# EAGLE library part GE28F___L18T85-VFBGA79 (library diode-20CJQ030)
Intel StrataFlash® Wireless Memory (L18) 28F640L18, 28F128L18, 28F256L18 Package: VFBGA-79 Description: The Intel StrataFlash® wireless memory (L18) device is the latest generation of Intel StrataFlash® memory devices featuring flexible, multiple-partition, dual operation. It provides high performance synchronous-burst read mode and asynchronous read mode using 1.8 V lowvoltage, multi-level cell (MLC) technology. High performance Read-While-Write/Erase -85 ns initial access -54 MHz with zero wait state, 14 ns clock-todata output synchronous-burst mode -25 ns asynchronous-page mode -4-, 8-, 16-, and continuous-word burst mode -Burst suspend -Programmable WAIT configuration -Buffered Enhanced Factory Programming (Buffered EFP): 5 µs/byte (Typ) -1.8 V low-power buffered and non-buffered programming at 7 µs/byte (Typ) Architecture -Asymmetrically-blocked architecture -Multiple 8-Mbit partitions: 64Mb and 128Mb devices -Multiple 16-Mbit partitions: 256Mb devices -Four 16-Kword parameter blocks: top or bottom configurations -64-Kword main blocks -Dual-operation: Read-While-Write (RWW) or Read-While-Erase (RWE) -Status register for partition and device status Power -1.7 V - 2.0 V VCC operation -I/O voltage: 1.35 V - 2.0 V, 1.7 V - 2.0 V -Standby current: 25 µA (Typ) -4-Word synchronous read current: 17 mA (Typ) at 54 MHz -Automatic Power Savings (APS) mode Please send any comments to: messi@users.sourceforge.net
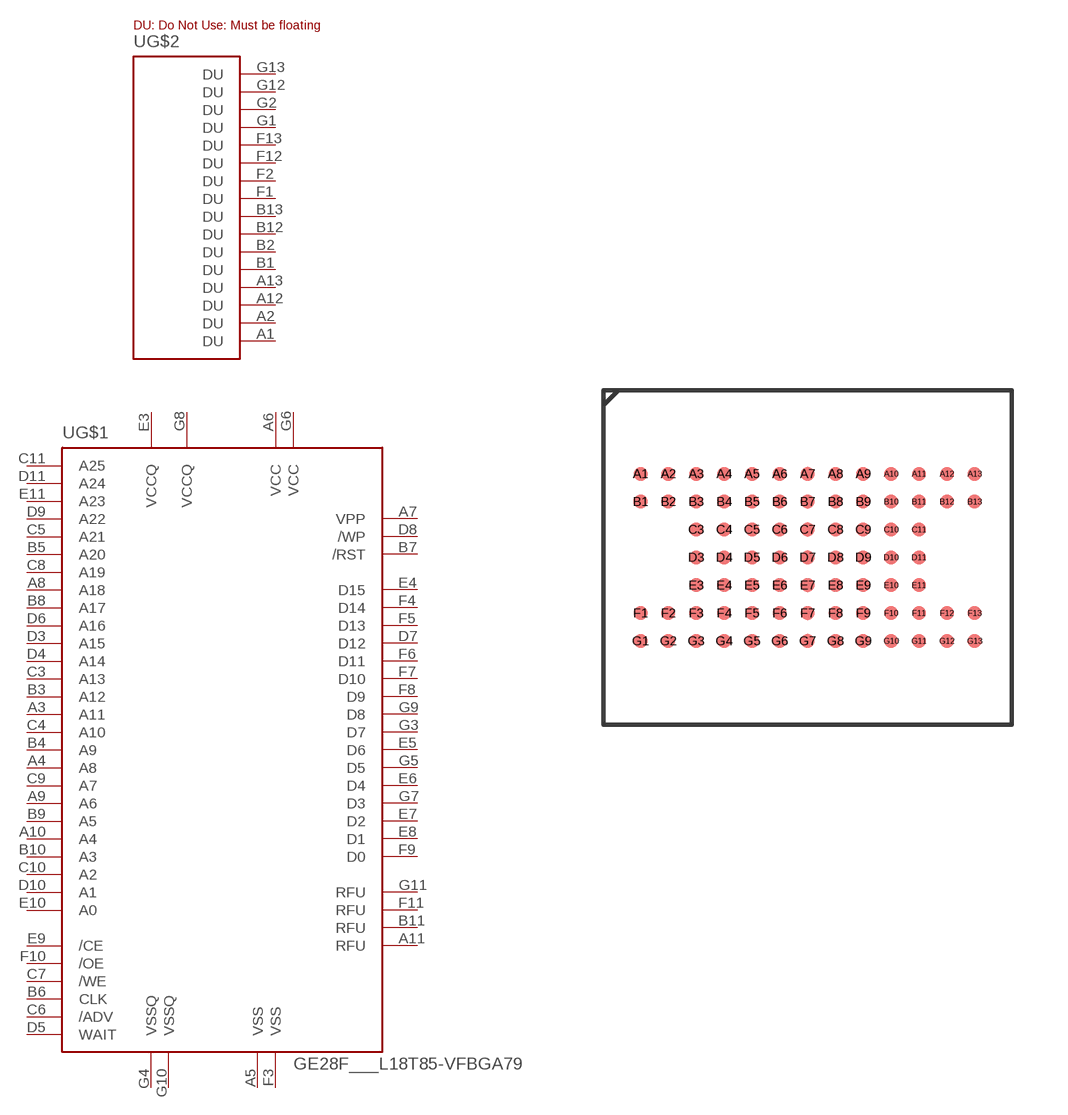
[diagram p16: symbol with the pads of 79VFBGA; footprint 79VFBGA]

Designator prefix U; gates G$1=GE28F_79VBGA G$2=GE28F_79VFBGA_DU

## GE28F___L18T85-VFBGA79  [79VFBGA]
A1  G$2:DU
A2  G$2:DU
A3  G$1:A11  in
A4  G$1:A8  in
A5  G$1:VSS  pwr
A6  G$1:VCC  in
A7  G$1:VPP  pwr
A8  G$1:A18  in
A9  G$1:A6  in
A10  G$1:A4  in
A11  G$1:RFU  nc
A12  G$2:DU
A13  G$2:DU
B1  G$2:DU
B2  G$2:DU
B3  G$1:A12  in
B4  G$1:A9  in
B5  G$1:A20  in
B6  G$1:CLK  in
B7  G$1:/RST  in
B8  G$1:A17  in
B9  G$1:A5  in
B10  G$1:A3  in
B11  G$1:RFU  nc
B12  G$2:DU
B13  G$2:DU
C3  G$1:A13  in
C4  G$1:A10  in
C5  G$1:A21  in
C6  G$1:/ADV  in
C7  G$1:/WE  in
C8  G$1:A19  in
C9  G$1:A7  in
C10  G$1:A2  in
C11  G$1:A25  in
D3  G$1:A15  in
D4  G$1:A14  in
D5  G$1:WAIT  out
D6  G$1:A16  in
D7  G$1:D12
D8  G$1:/WP  in
D9  G$1:A22  in
D10  G$1:A1  in
D11  G$1:A24  in
E3  G$1:VCCQ  in
E4  G$1:D15
E5  G$1:D6
E6  G$1:D4
E7  G$1:D2
E8  G$1:D1
E9  G$1:/CE  in
E10  G$1:A0  in
E11  G$1:A23  in
F1  G$2:DU
F2  G$2:DU
F3  G$1:VSS  pwr
F4  G$1:D14
F5  G$1:D13
F6  G$1:D11
F7  G$1:D10
F8  G$1:D9
F9  G$1:D0
F10  G$1:/OE  in
F11  G$1:RFU  nc
F12  G$2:DU
F13  G$2:DU
G1  G$2:DU
G2  G$2:DU
G3  G$1:D7
G4  G$1:VSSQ  pwr
G5  G$1:D5
G6  G$1:VCC  in
G7  G$1:D3
G8  G$1:VCCQ  in
G9  G$1:D8
G10  G$1:VSSQ  pwr
G11  G$1:RFU  nc
G12  G$2:DU
G13  G$2:DU

## Footprint 79VFBGA (pad centres in mm)
256-Mbit, 79-Ball VF BGA Package package with a 7 x 13 active-ball matrix pitch: 0.75 mm balldiameter: 0.375 Please send any comments to: messi@users.sourceforge.net
smd 0.375 x 0.375: A1 -4.5,2.25; A2 -3.75,2.25; A3 -3,2.25; A4 -2.25,2.25; A5 -1.5,2.25; A6 -0.75,2.25; A7 0,2.25; A8 0.75,2.25; A9 1.5,2.25; A10 2.25,2.25; A11 3,2.25; A12 3.75,2.25; A13 4.5,2.25; B1 -4.5,1.5; B2 -3.75,1.5; B3 -3,1.5; B4 -2.25,1.5; B5 -1.5,1.5; B6 -0.75,1.5; B7 0,1.5; B8 0.75,1.5; B9 1.5,1.5; B10 2.25,1.5; B11 3,1.5; B12 3.75,1.5; B13 4.5,1.5; C3 -3,0.75; C4 -2.25,0.75; C5 -1.5,0.75; C6 -0.75,0.75; C7 0,0.75; C8 0.75,0.75; C9 1.5,0.75; C10 2.25,0.75; C11 3,0.75; D3 -3,0; D4 -2.25,0; D5 -1.5,0; D6 -0.75,0; D7 0,0; D8 0.75,0; D9 1.5,0; D10 2.25,0; D11 3,0; E3 -3,-0.75; E4 -2.25,-0.75; E5 -1.5,-0.75; E6 -0.75,-0.75; E7 0,-0.75; E8 0.75,-0.75; E9 1.5,-0.75; E10 2.25,-0.75; E11 3,-0.75; F1 -4.5,-1.5; F2 -3.75,-1.5; F3 -3,-1.5; F4 -2.25,-1.5; F5 -1.5,-1.5; F6 -0.75,-1.5; F7 0,-1.5; F8 0.75,-1.5; F9 1.5,-1.5; F10 2.25,-1.5; F11 3,-1.5; F12 3.75,-1.5; F13 4.5,-1.5; G1 -4.5,-2.25; G2 -3.75,-2.25; G3 -3,-2.25; G4 -2.25,-2.25; G5 -1.5,-2.25; G6 -0.75,-2.25; G7 0,-2.25; G8 0.75,-2.25; G9 1.5,-2.25; G10 2.25,-2.25; G11 3,-2.25; G12 3.75,-2.25; G13 4.5,-2.25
